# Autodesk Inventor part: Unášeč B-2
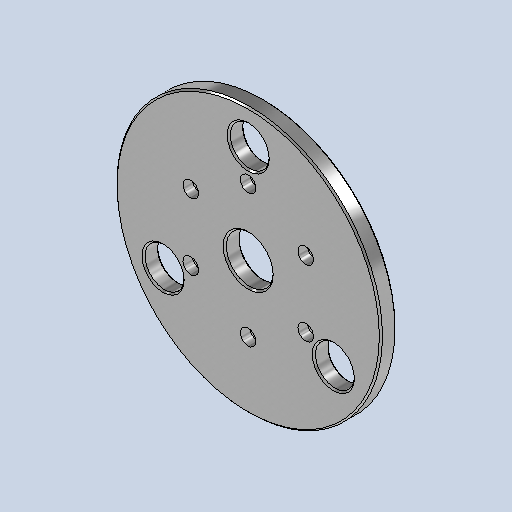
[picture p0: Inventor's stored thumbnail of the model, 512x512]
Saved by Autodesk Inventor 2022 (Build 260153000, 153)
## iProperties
Created: 2025-05
Part Number: Unášeč B-2
Material: Všeobecné
Document SubType Name: Modeling
Designer: jbart
Density: 1 g/cm^3
Appearance: Broušená
Mass: 1605.53 g
Surface Area: 1995.8 cm^2
Volume: 1605.53 cm^3
Author: jbart
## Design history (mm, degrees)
sketch "Náčrt1"
  geometry: L1 (0, 126)-(109.119, -63); L2 (109.119, -63)-(-109.119, -63); L3 (-109.119, -63)-(0, 126); L4 (0, 126)-(0, 0); L5 (0, 0)-(-109.119, -63); L6 (0, 0)-(109.119, -63); C1 r 25 at (0, 126); C2 r 25 at (-109.119, -63); C3 r 25 at (109.119, -63); C4 r 170 at (0, 0); C5 r 30 at (0, 0); 1 further point
  constraints: 12 end point, 6 coincident, 5 centre point, 1 vertical, 7 other
  dimensions: "d0" = 126 distance of L4.end L1.end; "d1" = 50 diameter of C1; "d2" = 50 diameter of C2; "d3" = 50 diameter of C3; "d4" = 340 diameter of C4; "d5" = 60 diameter of C5
extrude "Vysunutí1" new body sketch "Náčrt1" distance "d6" = 20; taper "d7" = 0 deg
sketch "Náčrt2"
  geometry: L1 (0, 0)-(-73.612, 42.5); L2 (0, 0)-(0, 85); A1 r 85 centre (0, 0) between (0, 85) and (-73.612, 42.5); 2 further points
  constraints: 4 end point, 2 coincident, 2 point on circle, 1 centre point, 1 vertical
  dimensions: "d8" = 170 diameter of A1; "d9" = 60 deg angle of L2 L1
hole "Díra1" sketch "Náčrt2" at (-73.612, 42.5) diameter "d14" = 13; stored, may be unused: countersink angle "d18" = 90 deg, drill point angle "d20" = 118 deg; dims "d15" = 6, "d16" = 20, "d17" = 12, "d19" = 8
chamfer "Zkosení1" distance "d21" = 2; stored, may be unused: second distance "d22" = 2, angle "d23" = 45 deg
pattern_circular "Kruhové pole1" dims angle "d25" = 360 deg
node "Těleso1"
